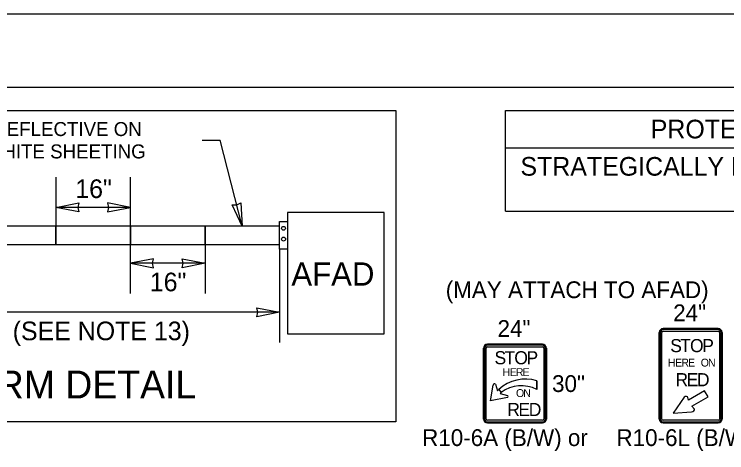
# Model space of a CAD drawing. Extents: x 99999.1 to 100095.7, y 99995 to 100010.7.
# Drawn here: x 100049.325 to 100052.384, y 100008.806 to 100010.687 of the extents above; entities that cross this region are included whole.
import ezdxf

# ---------------------------------------------------------------- set-up
doc = ezdxf.new("R2010")
doc.units = 0
for name, color, linetype in [('SH_GI_PlotLimits', 7, 'Continuous'), ('SH_GI_SheetBorder', 7, 'Continuous'), ('SH_TI_Tables', 7, 'Continuous'), ('TR_SN_ConstructionSigns', 7, 'Continuous'), ('TR_WZ_WorkZoneDetails', 7, 'Continuous')]:
    doc.layers.add(name, color=color, linetype=linetype)

msp = doc.modelspace()

# ---------------------------------------------------------------- linework, layer by layer
at = {"layer": 'SH_GI_PlotLimits'}
msp.add_lwpolyline([(100039.0625, 99999.6875), (100056.0625, 99999.6875), (100056.0625, 100010.6875), (100039.0625, 100010.6875)], close=True, dxfattribs=at)
at = {"layer": 'SH_GI_SheetBorder'}
msp.add_line((100040, 100010.375), (100055.75, 100010.375), dxfattribs=at)
at = {"layer": 'SH_TI_Tables'}
for p, q in [((100051.4347, 100009.843), (100051.4347, 100010.275)), ((100051.4347, 100010.275), (100055.65, 100010.275)), ((100051.4347, 100010.115), (100055.65, 100010.115)), ((100051.4347, 100009.843), (100055.65, 100009.843))]:
    msp.add_line(p, q, dxfattribs=at)
at = {"layer": 'TR_SN_ConstructionSigns'}
for p, q in [((100052.0939, 100009.3222), (100052.0939, 100008.951)), ((100052.0939, 100008.951), (100052.0939, 100009.3222)), ((100052.0939, 100009.3222), (100052.0939, 100008.951)), ((100052.0981, 100009.3222), (100052.0981, 100008.951)), ((100052.1052, 100008.951), (100052.1052, 100009.3222)), ((100052.347, 100009.3391), (100052.1108, 100009.3391)), ((100052.1108, 100009.3391), (100052.347, 100009.3391)), ((100052.347, 100009.3391), (100052.1108, 100009.3391)), ((100052.347, 100009.3349), (100052.1108, 100009.3349)), ((100052.1108, 100009.3279), (100052.347, 100009.3279)), ((100052.3527, 100009.3222), (100052.3527, 100008.951)), ((100052.3597, 100008.951), (100052.3597, 100009.3222)), ((100052.3639, 100008.951), (100052.3639, 100009.3222)), ((100052.3639, 100009.3222), (100052.3639, 100008.951)), ((100052.3639, 100008.951), (100052.3639, 100009.3222)), ((100051.5928, 100009.2716), (100051.3566, 100009.2716)), ((100051.3566, 100009.2716), (100051.5928, 100009.2716)), ((100051.5928, 100009.2716), (100051.3566, 100009.2716)), ((100051.3566, 100009.2716), (100051.5928, 100009.2716)), ((100051.5928, 100009.2674), (100051.3566, 100009.2674)), ((100051.3566, 100009.2604), (100051.5928, 100009.2604)), ((100051.3397, 100009.2547), (100051.3397, 100008.951)), ((100051.3397, 100008.951), (100051.3397, 100009.2547)), ((100051.3397, 100009.2547), (100051.3397, 100008.951)), ((100051.3397, 100008.951), (100051.3397, 100009.2547)), ((100051.3439, 100009.2547), (100051.3439, 100008.951)), ((100051.351, 100008.951), (100051.351, 100009.2547)), ((100051.5985, 100009.2547), (100051.5985, 100008.951)), ((100051.6055, 100008.951), (100051.6055, 100009.2547)), ((100051.6097, 100008.951), (100051.6097, 100009.2547)), ((100051.6097, 100009.2547), (100051.6097, 100008.951)), ((100051.6097, 100008.951), (100051.6097, 100009.2547)), ((100051.6097, 100009.2547), (100051.6097, 100008.951)), ((100051.5692, 100009.1152), (100051.5689, 100009.0774)), ((100051.5689, 100009.0774), (100051.5692, 100009.1152)), ((100051.3692, 100009.0297), (100051.3815, 100009.0967)), ((100051.3912, 100009.1011), (100051.3997, 100009.0719)), ((100051.3997, 100009.0719), (100051.4054, 100009.0776)), ((100051.4054, 100009.0776), (100051.4159, 100009.0642)), ((100051.4054, 100009.0776), (100051.4159, 100009.0642)), ((100051.4423, 100009.0433), (100051.3692, 100009.0297)), ((100051.4159, 100009.0642), (100051.4117, 100009.0599)), ((100051.4117, 100009.0599), (100051.4424, 100009.0517)), ((100052.2015, 100009.0445), (100052.1541, 100008.9764)), ((100052.22, 100009.0321), (100052.2166, 100009.0435)), ((100052.289, 100009.0719), (100052.22, 100009.0321)), ((100052.234, 100009.0061), (100052.3037, 100009.0463)), ((100052.3037, 100009.0463), (100052.289, 100009.0719)), ((100052.1541, 100008.9764), (100052.2332, 100008.9819)), ((100052.2451, 100008.9938), (100052.234, 100009.0061)), ((100051.5928, 100008.9454), (100051.3566, 100008.9454)), ((100051.3566, 100008.9383), (100051.5928, 100008.9383)), ((100051.3566, 100008.9341), (100051.5928, 100008.9341)), ((100051.5928, 100008.9341), (100051.3566, 100008.9341)), ((100051.3566, 100008.9341), (100051.5928, 100008.9341)), ((100051.5928, 100008.9341), (100051.3566, 100008.9341)), ((100052.347, 100008.9454), (100052.1108, 100008.9454)), ((100052.1108, 100008.9383), (100052.347, 100008.9383)), ((100052.1108, 100008.9341), (100052.347, 100008.9341)), ((100052.347, 100008.9341), (100052.1108, 100008.9341)), ((100052.1108, 100008.9341), (100052.347, 100008.9341))]:
    msp.add_line(p, q, dxfattribs=at)
for centre, radius, start, end in [((100052.1108, 100009.3222), 0.0169, 90, 180), ((100052.1108, 100009.3222), 0.0169, 90, 180), ((100052.1108, 100009.3222), 0.0169, 90, 180), ((100052.1108, 100009.3222), 0.0127, 90, 180), ((100052.1108, 100009.3222), 0.00562, 90, 180), ((100052.347, 100009.3222), 0.0169, 0, 90), ((100052.347, 100009.3222), 0.0169, 0, 90), ((100052.347, 100009.3222), 0.0169, 0, 90), ((100052.347, 100009.3222), 0.0127, 0, 90), ((100052.347, 100009.3222), 0.00562, 0, 90), ((100051.3566, 100009.2547), 0.0169, 90, 180), ((100051.3566, 100009.2547), 0.0169, 90, 180), ((100051.3566, 100009.2547), 0.0169, 90, 180), ((100051.3566, 100009.2547), 0.0169, 90, 180), ((100051.3566, 100009.2547), 0.0127, 90, 180), ((100051.3566, 100009.2547), 0.00562, 90, 180), ((100051.5928, 100009.2547), 0.0169, 0, 90), ((100051.5928, 100009.2547), 0.0169, 0, 90), ((100051.5928, 100009.2547), 0.0169, 0, 90), ((100051.5928, 100009.2547), 0.0169, 0, 90), ((100051.5928, 100009.2547), 0.0127, 0, 90), ((100051.5928, 100009.2547), 0.00562, 0, 90), ((100051.5208, 100008.9504), 0.1718, 73.6434, 132.2131), ((100051.5208, 100008.9504), 0.1718, 73.6434, 132.2131), ((100051.5028, 100008.9509), 0.1427, 62.4149, 127.4769), ((100051.5028, 100008.9509), 0.1427, 62.4149, 127.4769), ((100051.3566, 100008.951), 0.0169, 180, 270), ((100051.3566, 100008.951), 0.0169, 180, 270), ((100051.3566, 100008.951), 0.0169, 180, 270), ((100051.3566, 100008.951), 0.0169, 180, 270), ((100051.3566, 100008.951), 0.0127, 180, 270), ((100051.3566, 100008.951), 0.00562, 180, 270), ((100051.5928, 100008.951), 0.0169, 270, 0), ((100051.5928, 100008.951), 0.0169, 270, 0), ((100051.5928, 100008.951), 0.0169, 270, 0), ((100051.5928, 100008.951), 0.0127, 270, 0), ((100051.5928, 100008.951), 0.00562, 270, 0), ((100051.5928, 100008.951), 0.0169, 270, 0), ((100052.1108, 100008.951), 0.0169, 180, 270), ((100052.1108, 100008.951), 0.0169, 180, 270), ((100052.1108, 100008.951), 0.0169, 180, 270), ((100052.1108, 100008.951), 0.0127, 180, 270), ((100052.1108, 100008.951), 0.00562, 180, 270), ((100052.347, 100008.951), 0.0169, 270, 0), ((100052.347, 100008.951), 0.0169, 270, 0), ((100052.347, 100008.951), 0.0169, 270, 0), ((100052.347, 100008.951), 0.0127, 270, 0), ((100052.347, 100008.951), 0.00562, 270, 0)]:
    msp.add_arc(centre, radius, start, end, dxfattribs=at)
for centre, major_axis, ratio, start_param, end_param in [((100051.3873, 100009.0968), (-0.00583, -0.00008), 0.989437, 3.962549, 6.283185), ((100051.4403, 100009.0475), (-0.00414, 0.00215), 0.999053, 2.490568, 4.712389), ((100052.2076, 100009.0406), (0.00841, 0.00485), 0.700347, 5.977036, 8.198856), ((100052.2368, 100008.9893), (-0.00822, -0.00474), 0.700347, 0.771965, 3.092601)]:
    msp.add_ellipse(centre, major_axis=major_axis, ratio=ratio, start_param=start_param, end_param=end_param, dxfattribs=at)
at = {"layer": 'TR_WZ_WorkZoneDetails'}
for p, q in [((100050.1326, 100010.147), (100050.2088, 100010.147)), ((100050.3043, 100009.779), (100050.2088, 100010.147)), ((100049.5043, 100009.989), (100049.5043, 100009.779)), ((100049.8243, 100009.779), (100049.8243, 100009.989)), ((100049.8243, 100009.859), (100049.5043, 100009.859)), ((100049.8243, 100009.489), (100049.8243, 100009.699)), ((100050.1443, 100009.699), (100050.1443, 100009.489)), ((100050.4643, 100009.6797), (100050.4643, 100009.279)), ((100050.1443, 100009.619), (100049.8243, 100009.619)), ((100050.4643, 100009.409), (100048.6643, 100009.409))]:
    msp.add_line(p, q, dxfattribs=at)
for points in [[(100047.6374, 100010.275), (100050.9639, 100010.275), (100050.9639, 100008.939), (100047.6374, 100008.939)], [(100049.5043, 100009.859), (100049.6026, 100009.8783), (100049.5981, 100009.859), (100049.6026, 100009.8397)], [(100049.8243, 100009.859), (100049.7261, 100009.8783), (100049.7306, 100009.859), (100049.7261, 100009.8397)], [(100050.3043, 100009.779), (100050.2611, 100009.8693), (100050.2809, 100009.8697), (100050.2984, 100009.879)], [(100050.4643, 100009.7983), (100050.4977, 100009.7983), (100050.4977, 100009.6797), (100050.4643, 100009.6797)], [(100049.8243, 100009.619), (100049.9226, 100009.5997), (100049.9181, 100009.619), (100049.9226, 100009.6383)], [(100050.1443, 100009.619), (100050.0461, 100009.5997), (100050.0506, 100009.619), (100050.0461, 100009.6383)], [(100050.4643, 100009.409), (100050.3661, 100009.3897), (100050.3706, 100009.409), (100050.3661, 100009.4283)]]:
    msp.add_lwpolyline(points, close=True, dxfattribs=at)
for points in [[(100050.4977, 100009.6797), (100050.4977, 100009.3163), (100050.9139, 100009.3163), (100050.9139, 100009.8374), (100050.4977, 100009.8374), (100050.4977, 100009.7983), (100050.4977, 100009.6797)], [(100050.9139, 100009.8374), (100050.4977, 100009.8374), (100050.4977, 100009.3163), (100050.9139, 100009.3163), (100050.9139, 100009.8374)], [(100050.4643, 100009.779), (100048.6643, 100009.779), (100048.6643, 100009.699), (100050.4643, 100009.699), (100050.4643, 100009.779)], [(100049.1843, 100009.699), (100049.5043, 100009.699), (100049.5043, 100009.779), (100049.1843, 100009.779), (100049.1843, 100009.699)], [(100049.5043, 100009.699), (100049.8243, 100009.699), (100049.8243, 100009.779), (100049.5043, 100009.779), (100049.5043, 100009.699)], [(100049.8243, 100009.699), (100050.1443, 100009.699), (100050.1443, 100009.779), (100049.8243, 100009.779), (100049.8243, 100009.699)], [(100050.1443, 100009.699), (100050.4643, 100009.699), (100050.4643, 100009.779), (100050.1443, 100009.779), (100050.1443, 100009.699)]]:
    msp.add_lwpolyline(points, dxfattribs=at)
for centre, radius in [((100050.4813, 100009.7693), 0.00828), ((100050.4813, 100009.7229), 0.00855)]:
    msp.add_circle(centre, radius, dxfattribs=at)

# ---------------------------------------------------------------- texts
at = {"layer": 'SH_TI_Tables'}
for s, p in [('PROTECTIVE VEHICLE ROLL AHEAD DISTANCE = R', (100052.0577, 100010.155)), ('STRATEGICALLY POSITION WORK VEHICLE TO PROTECT WORK CREW.', (100051.4984, 100009.995))]:
    msp.add_text(s, height=0.08, rotation=360, dxfattribs=at).set_placement(p)
at = {"layer": 'TR_SN_ConstructionSigns'}
for s, p in [('(MAY ATTACH TO AFAD)', (100051.1775, 100009.4696)), ('24"', (100052.1539, 100009.3706)), ('24"', (100051.3999, 100009.3031)), ('30"', (100051.634, 100009.0669)), ('R10-6A (B/W) or', (100051.0761, 100008.8351)), ('R10-6L (B/W)', (100051.9104, 100008.8351))]:
    msp.add_text(s, height=0.072, rotation=360, dxfattribs=at).set_placement(p)
for s, height, p in [('S', 0.0562, (100052.1412, 100009.2379)), ('T', 0.0562, (100052.1839, 100009.2379)), ('O', 0.0562, (100052.2261, 100009.2379)), ('P', 0.0562, (100052.2784, 100009.2379)), ('S', 0.0562, (100051.387, 100009.1858)), ('T', 0.0562, (100051.4297, 100009.1858)), ('O', 0.0562, (100051.4719, 100009.1858)), ('P', 0.0562, (100051.5242, 100009.1858)), ('H', 0.0338, (100052.1312, 100009.176)), ('E', 0.0338, (100052.1623, 100009.176)), ('R', 0.0338, (100052.1889, 100009.176)), ('E', 0.0338, (100052.2176, 100009.176)), ('O', 0.0338, (100052.2723, 100009.176)), ('N', 0.0338, (100052.3037, 100009.176)), ('H', 0.0338, (100051.421, 100009.1352)), ('E', 0.0338, (100051.4521, 100009.1352)), ('R', 0.0338, (100051.4788, 100009.1352)), ('E', 0.0338, (100051.5074, 100009.1352)), ('R', 0.0562, (100052.1637, 100009.0916)), ('E', 0.0562, (100052.2115, 100009.0916)), ('D', 0.0562, (100052.2559, 100009.0916)), ('O', 0.0338, (100051.4791, 100009.0452)), ('N', 0.0338, (100051.5105, 100009.0452)), ('R', 0.0562, (100051.4417, 100008.9636)), ('E', 0.0562, (100051.4895, 100008.9636)), ('D', 0.0562, (100051.5339, 100008.9636))]:
    msp.add_text(s, height=height, dxfattribs=at).set_placement(p)
at = {"layer": 'TR_WZ_WorkZoneDetails'}
for s, height, p in [('GATE ARM SHALL BE FULLY RETROREFLECTIVE ON', 0.06, (100047.8352, 100010.165)), ('BOTH SIDES WITH ALTERNATING RED/WHITE SHEETING', 0.06, (100047.6874, 100010.069)), ('16"', 0.08, (100049.5873, 100009.899)), ('AFAD', 0.1, (100050.5149, 100009.5231)), ('16"', 0.08, (100049.9073, 100009.499)), ('78" MIN (SEE NOTE 13)', 0.08, (100048.9061, 100009.289))]:
    msp.add_text(s, height=height, dxfattribs=at).set_placement(p)
msp.add_text('AFAD GATE ARM DETAIL', height=0.12, rotation=360, dxfattribs=at).set_placement((100048.1893, 100009.039))

doc.saveas('drawing.dxf')
